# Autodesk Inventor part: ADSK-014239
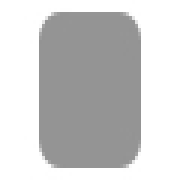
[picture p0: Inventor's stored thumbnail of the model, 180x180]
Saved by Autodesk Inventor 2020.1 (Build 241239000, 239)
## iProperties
Created: 2019-01
Part Number: ADSK-014239
Material: Stahl, weich
Document SubType Name: Modeling
Designer: lutzd
Language: de-DE
Size Designation: 5 x 39,384472 x 39,384472
Categories: <MemberInstance><Categories><Category DisplayName="Sonstige Bauteile" InternalName="5aa15e00-363f-49f2-933f-16f664388e3f" Mnemonic="OTHER"><Category DisplayName
Mass: 60.0398 g
Surface Area: 38.0412 cm^2
Volume: 7.64838 cm^3
Density: 7.85 g/cm^3
Appearance: Halbpoliert
IsCustomPart: 1
DocNumber: ADSK-014239
Folder: 01 - Themengebiete\Simplification\01 - Packaging machine\ADSK-014200\Frame\
VDS_Category: 3D Komponenten
VDS_NumSchm: Autodesk
Dimensions: 39,4x39,4x5 mm
Mass: 0,06 kg
Title: end cap
Author: lutzd
Revision Number: -
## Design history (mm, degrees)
sketch "Sketch1"
  geometry: L1 (0, 20.175)-(0, -21.446); L2 (-20.203, 0)-(20.169, 0); L3 (-19.692, 19.692)-(19.692, 19.692); L4 (19.692, 19.692)-(19.692, -19.692); L5 (19.692, -19.692)-(-19.692, -19.692); L6 (-19.692, -19.692)-(-19.692, 19.692); 1 further point
  constraints: 12 end point, 2 horizontal, 2 parallel, 2 point on line, 1 perpendicular, 1 vertical
  dimensions: "d0" = 39.38447 distance between parallel lines of L5 L3 (= height); "d1" = 19.69224 distance between parallel lines of L2 L3 (= 0.5 x height); "d2" = 39.38447 distance between parallel lines of L6 L4 (= width); "d3" = 19.69224 distance between parallel lines of L6 L1 (= 0.5 x width)
extrude "Extrusion1" new body sketch "Sketch1" distance "d4" = 5 (= thickness); taper "d5" = 0 deg
fillet "Fillet1" dims "d6" = 5 (= fillet), "d7" = 0, "fillet" = 5 [user parameter; used in 1 equation term]
chamfer "Chamfer1" distance "d8" = 0 (computed from chamfer); stored, may be unused: second distance "d9" = 2, angle "d10" = 45 deg; dims "d11" = 0, "chamfer" = 0 [user parameter; used in 1 equation term]
body "Solid1"
other parameters: "thickness" = 5 [user parameter; used in 1 equation term], "width" = 39.38447 [user parameter; used in 2 equation terms], "height" = 39.38447 [user parameter; used in 2 equation terms]
